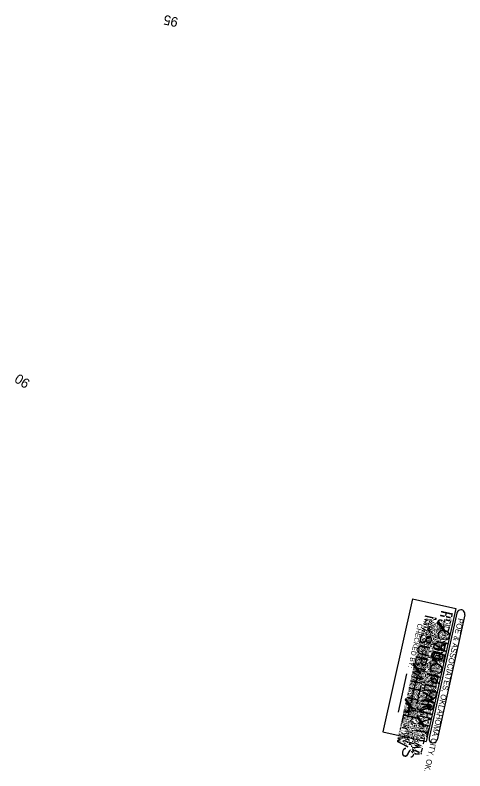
# Model space of a CAD drawing. Extents: x 2149887 to 2151449, y 143603 to 146901.
# Drawn here: x 2150415 to 2150971, y 143603 to 144538 of the extents above; entities that cross this region are included whole.
import ezdxf

# ---------------------------------------------------------------- set-up
doc = ezdxf.new("R2010")
doc.units = 0
for name, color, linetype in [('SHT_Stamp_30_Submit', 7, 'Continuous'), ('SHT_Stamp_70_Submit', 7, 'Continuous'), ('SHT_Stamp_Check_Print', 7, 'Continuous'), ('SHT_Stamp_Est_Inf', 7, 'Continuous'), ('SHT_Stamp_FFR', 7, 'Continuous'), ('SHT_Stamp_Info_Material', 7, 'Continuous'), ('SHT_Stamp_No_Const', 7, 'Continuous'), ('SHT_Stamp_No_Design', 7, 'Continuous'), ('SHT_Stamp_Plan_Hand', 7, 'Continuous'), ('SHT_Stamp_Pre_Plan', 7, 'Continuous'), ('SHT_Stamp_Prop_RW', 7, 'Continuous'), ('SHT_Stamp_Ret_Sub', 7, 'Continuous'), ('SHT_Stamp_Rev_Prop_RW', 7, 'Continuous'), ('SHT_Stamp_Rev_Sheet', 7, 'Continuous'), ('SHT_Stamp_RW_Utilities_Meeting', 7, 'Continuous'), ('SHT_Stamp_RW_Utilities_Review', 7, 'Continuous'), ('SHT_Stamp_Send_Comments', 7, 'Continuous'), ('TOPO_DRAIN_Manhole', 7, 'Continuous')]:
    doc.layers.add(name, color=color, linetype=linetype)

msp = doc.modelspace()

# ---------------------------------------------------------------- linework, layer by layer
at = {"layer": 'SHT_Stamp_30_Submit'}
for p, q in [((2150906.22, 143815.49), (2150869.69, 143651.21)), ((2150906.22, 143815.49), (2150959.86, 143803.56)), ((2150959.86, 143803.56), (2150923.34, 143639.28)), ((2150961.22, 143798.13), (2150926.86, 143643.62)), ((2150970.98, 143795.96), (2150936.62, 143641.44)), ((2150929.87, 143746.55), (2150929.53, 143745.06)), ((2150929.53, 143745.06), (2150936.27, 143735.59)), ((2150929.62, 143745.44), (2150936.35, 143735.98)), ((2150929.67, 143745.68), (2150936.41, 143736.22)), ((2150929.87, 143746.55), (2150936.6, 143737.09)), ((2150936.6, 143737.09), (2150936.27, 143735.59)), ((2150869.69, 143651.21), (2150923.34, 143639.28))]:
    msp.add_line(p, q, dxfattribs=at)
for centre, start, end in [((2150966.11, 143797.04), 347.45904, 167.46382), ((2150931.75, 143642.51), 167.46382, 347.4686)]:
    msp.add_arc(centre, 5, start, end, dxfattribs=at)
at = {"layer": 'SHT_Stamp_70_Submit'}
for p, q in [((2150906.22, 143815.49), (2150869.69, 143651.21)), ((2150906.22, 143815.49), (2150959.86, 143803.56)), ((2150959.86, 143803.56), (2150923.34, 143639.28)), ((2150961.22, 143798.13), (2150926.86, 143643.62)), ((2150970.98, 143795.96), (2150936.62, 143641.44)), ((2150929.87, 143746.55), (2150929.53, 143745.06)), ((2150929.53, 143745.06), (2150936.27, 143735.59)), ((2150929.62, 143745.44), (2150936.35, 143735.98)), ((2150929.67, 143745.68), (2150936.41, 143736.22)), ((2150929.87, 143746.55), (2150936.6, 143737.09)), ((2150936.6, 143737.09), (2150936.27, 143735.59)), ((2150869.69, 143651.21), (2150923.34, 143639.28))]:
    msp.add_line(p, q, dxfattribs=at)
for centre, start, end in [((2150966.11, 143797.04), 347.45904, 167.46382), ((2150931.75, 143642.51), 167.46382, 347.4686)]:
    msp.add_arc(centre, 5, start, end, dxfattribs=at)
at = {"layer": 'SHT_Stamp_Check_Print'}
for p, q in [((2150906.22, 143815.49), (2150869.69, 143651.21)), ((2150906.22, 143815.49), (2150959.86, 143803.56)), ((2150959.86, 143803.56), (2150923.34, 143639.28)), ((2150961.22, 143798.13), (2150926.86, 143643.62)), ((2150970.98, 143795.96), (2150936.62, 143641.44)), ((2150899.04, 143722.75), (2150888.5, 143675.39)), ((2150911.51, 143719.98), (2150900.98, 143672.62)), ((2150869.69, 143651.21), (2150923.34, 143639.28))]:
    msp.add_line(p, q, dxfattribs=at)
for centre, start, end in [((2150966.11, 143797.04), 347.45904, 167.46382), ((2150931.75, 143642.51), 167.46382, 347.4686)]:
    msp.add_arc(centre, 5, start, end, dxfattribs=at)
at = {"layer": 'SHT_Stamp_Est_Inf'}
for p, q in [((2150906.22, 143815.49), (2150869.69, 143651.21)), ((2150906.22, 143815.49), (2150959.86, 143803.56)), ((2150959.86, 143803.56), (2150923.34, 143639.28)), ((2150961.22, 143798.13), (2150926.86, 143643.62)), ((2150970.98, 143795.96), (2150936.62, 143641.44)), ((2150869.69, 143651.21), (2150923.34, 143639.28))]:
    msp.add_line(p, q, dxfattribs=at)
for centre, start, end in [((2150966.11, 143797.04), 347.45904, 167.46382), ((2150931.75, 143642.51), 167.46382, 347.4686)]:
    msp.add_arc(centre, 5, start, end, dxfattribs=at)
at = {"layer": 'SHT_Stamp_FFR'}
for p, q in [((2150906.22, 143815.49), (2150869.69, 143651.21)), ((2150906.22, 143815.49), (2150959.86, 143803.56)), ((2150959.86, 143803.56), (2150923.34, 143639.28)), ((2150961.22, 143798.13), (2150926.86, 143643.62)), ((2150970.98, 143795.96), (2150936.62, 143641.44)), ((2150869.69, 143651.21), (2150923.34, 143639.28))]:
    msp.add_line(p, q, dxfattribs=at)
for centre, start, end in [((2150966.11, 143797.04), 347.45904, 167.46382), ((2150931.75, 143642.51), 167.46382, 347.4686)]:
    msp.add_arc(centre, 5, start, end, dxfattribs=at)
at = {"layer": 'SHT_Stamp_Info_Material'}
for p, q in [((2150906.22, 143815.49), (2150869.69, 143651.21)), ((2150906.22, 143815.49), (2150959.86, 143803.56)), ((2150959.86, 143803.56), (2150923.34, 143639.28)), ((2150961.22, 143798.13), (2150926.86, 143643.62)), ((2150970.98, 143795.96), (2150936.62, 143641.44)), ((2150869.69, 143651.21), (2150923.34, 143639.28))]:
    msp.add_line(p, q, dxfattribs=at)
for centre, start, end in [((2150966.11, 143797.04), 347.45904, 167.46382), ((2150931.75, 143642.51), 167.46382, 347.4686)]:
    msp.add_arc(centre, 5, start, end, dxfattribs=at)
at = {"layer": 'SHT_Stamp_No_Const'}
for p, q in [((2150906.22, 143815.49), (2150869.69, 143651.21)), ((2150906.22, 143815.49), (2150959.86, 143803.56)), ((2150959.86, 143803.56), (2150923.34, 143639.28)), ((2150961.22, 143798.13), (2150926.86, 143643.62)), ((2150970.98, 143795.96), (2150936.62, 143641.44)), ((2150869.69, 143651.21), (2150923.34, 143639.28))]:
    msp.add_line(p, q, dxfattribs=at)
for centre, start, end in [((2150966.11, 143797.04), 347.45904, 167.46382), ((2150931.75, 143642.51), 167.46382, 347.4686)]:
    msp.add_arc(centre, 5, start, end, dxfattribs=at)
at = {"layer": 'SHT_Stamp_No_Design'}
for p, q in [((2150906.22, 143815.49), (2150869.69, 143651.21)), ((2150906.22, 143815.49), (2150959.86, 143803.56)), ((2150959.86, 143803.56), (2150923.34, 143639.28)), ((2150961.22, 143798.13), (2150926.86, 143643.62)), ((2150970.98, 143795.96), (2150936.62, 143641.44)), ((2150869.69, 143651.21), (2150923.34, 143639.28))]:
    msp.add_line(p, q, dxfattribs=at)
for centre, start, end in [((2150966.11, 143797.04), 347.45904, 167.46382), ((2150931.75, 143642.51), 167.46382, 347.4686)]:
    msp.add_arc(centre, 5, start, end, dxfattribs=at)
at = {"layer": 'SHT_Stamp_Plan_Hand'}
for p, q in [((2150906.22, 143815.49), (2150869.69, 143651.21)), ((2150906.22, 143815.49), (2150959.86, 143803.56)), ((2150959.86, 143803.56), (2150923.34, 143639.28)), ((2150961.22, 143798.13), (2150926.86, 143643.62)), ((2150970.98, 143795.96), (2150936.62, 143641.44)), ((2150869.69, 143651.21), (2150923.34, 143639.28))]:
    msp.add_line(p, q, dxfattribs=at)
for centre, start, end in [((2150966.11, 143797.04), 347.45904, 167.46382), ((2150931.75, 143642.51), 167.46382, 347.4686)]:
    msp.add_arc(centre, 5, start, end, dxfattribs=at)
at = {"layer": 'SHT_Stamp_Pre_Plan'}
for p, q in [((2150906.22, 143815.49), (2150869.69, 143651.21)), ((2150906.22, 143815.49), (2150959.86, 143803.56)), ((2150959.86, 143803.56), (2150923.34, 143639.28)), ((2150961.22, 143798.13), (2150926.86, 143643.62)), ((2150970.98, 143795.96), (2150936.62, 143641.44)), ((2150869.69, 143651.21), (2150923.34, 143639.28))]:
    msp.add_line(p, q, dxfattribs=at)
for centre, start, end in [((2150966.11, 143797.04), 347.45904, 167.46382), ((2150931.75, 143642.51), 167.46382, 347.4686)]:
    msp.add_arc(centre, 5, start, end, dxfattribs=at)
at = {"layer": 'SHT_Stamp_Prop_RW'}
for p, q in [((2150906.22, 143815.49), (2150869.69, 143651.21)), ((2150906.22, 143815.49), (2150959.86, 143803.56)), ((2150959.86, 143803.56), (2150923.34, 143639.28)), ((2150961.22, 143798.13), (2150926.86, 143643.62)), ((2150970.98, 143795.96), (2150936.62, 143641.44)), ((2150907.58, 143735.96), (2150907.17, 143734.11)), ((2150907.17, 143734.11), (2150915.48, 143722.43)), ((2150907.27, 143734.58), (2150915.59, 143722.9)), ((2150907.34, 143734.88), (2150915.65, 143723.2)), ((2150907.58, 143735.96), (2150915.89, 143724.27)), ((2150915.89, 143724.27), (2150915.48, 143722.43)), ((2150869.69, 143651.21), (2150923.34, 143639.28))]:
    msp.add_line(p, q, dxfattribs=at)
for centre, start, end in [((2150966.11, 143797.04), 347.45904, 167.46382), ((2150931.75, 143642.51), 167.46382, 347.4686)]:
    msp.add_arc(centre, 5, start, end, dxfattribs=at)
at = {"layer": 'SHT_Stamp_Ret_Sub'}
for p, q in [((2150906.22, 143815.49), (2150869.69, 143651.21)), ((2150906.22, 143815.49), (2150959.86, 143803.56)), ((2150959.86, 143803.56), (2150923.34, 143639.28)), ((2150961.22, 143798.13), (2150926.86, 143643.62)), ((2150970.98, 143795.96), (2150936.62, 143641.44)), ((2150869.69, 143651.21), (2150923.34, 143639.28))]:
    msp.add_line(p, q, dxfattribs=at)
for centre, start, end in [((2150966.11, 143797.04), 347.45904, 167.46382), ((2150931.75, 143642.51), 167.46382, 347.4686)]:
    msp.add_arc(centre, 5, start, end, dxfattribs=at)
at = {"layer": 'SHT_Stamp_Rev_Prop_RW'}
for p, q in [((2150906.22, 143815.49), (2150869.69, 143651.21)), ((2150906.22, 143815.49), (2150959.86, 143803.56)), ((2150959.86, 143803.56), (2150923.34, 143639.28)), ((2150961.22, 143798.13), (2150926.86, 143643.62)), ((2150970.98, 143795.96), (2150936.62, 143641.44)), ((2150897.78, 143692.54), (2150897.37, 143690.7)), ((2150897.37, 143690.7), (2150905.68, 143679.01)), ((2150897.47, 143691.17), (2150905.79, 143679.48)), ((2150897.54, 143691.47), (2150905.85, 143679.78)), ((2150897.78, 143692.54), (2150906.09, 143680.86)), ((2150906.09, 143680.86), (2150905.68, 143679.01)), ((2150869.69, 143651.21), (2150923.34, 143639.28))]:
    msp.add_line(p, q, dxfattribs=at)
for centre, start, end in [((2150966.11, 143797.04), 347.45904, 167.46382), ((2150931.75, 143642.51), 167.46382, 347.4686)]:
    msp.add_arc(centre, 5, start, end, dxfattribs=at)
at = {"layer": 'SHT_Stamp_Rev_Sheet'}
for p, q in [((2150906.22, 143815.49), (2150869.69, 143651.21)), ((2150906.22, 143815.49), (2150959.86, 143803.56)), ((2150959.86, 143803.56), (2150923.34, 143639.28)), ((2150961.22, 143798.13), (2150926.86, 143643.62)), ((2150970.98, 143795.96), (2150936.62, 143641.44)), ((2150869.69, 143651.21), (2150923.34, 143639.28))]:
    msp.add_line(p, q, dxfattribs=at)
for centre, start, end in [((2150966.11, 143797.04), 347.45904, 167.46382), ((2150931.75, 143642.51), 167.46382, 347.4686)]:
    msp.add_arc(centre, 5, start, end, dxfattribs=at)
at = {"layer": 'SHT_Stamp_RW_Utilities_Meeting'}
for p, q in [((2150906.22, 143815.49), (2150869.69, 143651.21)), ((2150906.22, 143815.49), (2150959.86, 143803.56)), ((2150959.86, 143803.56), (2150923.34, 143639.28)), ((2150961.22, 143798.13), (2150926.86, 143643.62)), ((2150970.98, 143795.96), (2150936.62, 143641.44)), ((2150937.91, 143787.85), (2150937.5, 143786.01)), ((2150937.91, 143787.85), (2150946.22, 143776.17)), ((2150937.5, 143786.01), (2150945.81, 143774.32)), ((2150937.6, 143786.48), (2150945.92, 143774.79)), ((2150937.67, 143786.78), (2150945.98, 143775.1)), ((2150946.22, 143776.17), (2150945.81, 143774.32)), ((2150869.69, 143651.21), (2150923.34, 143639.28))]:
    msp.add_line(p, q, dxfattribs=at)
for centre, start, end in [((2150966.11, 143797.04), 347.45904, 167.46382), ((2150931.75, 143642.51), 167.46382, 347.4686)]:
    msp.add_arc(centre, 5, start, end, dxfattribs=at)
at = {"layer": 'SHT_Stamp_RW_Utilities_Review'}
for p, q in [((2150906.22, 143815.49), (2150869.69, 143651.21)), ((2150906.22, 143815.49), (2150959.86, 143803.56)), ((2150959.86, 143803.56), (2150923.34, 143639.28)), ((2150961.22, 143798.13), (2150926.86, 143643.62)), ((2150970.98, 143795.96), (2150936.62, 143641.44)), ((2150911.98, 143671.26), (2150911.57, 143669.42)), ((2150911.57, 143669.42), (2150919.89, 143657.73)), ((2150911.68, 143669.89), (2150919.99, 143658.2)), ((2150911.74, 143670.19), (2150920.06, 143658.5)), ((2150911.98, 143671.26), (2150920.3, 143659.58)), ((2150920.3, 143659.58), (2150919.89, 143657.73)), ((2150869.69, 143651.21), (2150923.34, 143639.28))]:
    msp.add_line(p, q, dxfattribs=at)
for centre, start, end in [((2150966.11, 143797.04), 347.45904, 167.46382), ((2150931.75, 143642.51), 167.46382, 347.4686)]:
    msp.add_arc(centre, 5, start, end, dxfattribs=at)
at = {"layer": 'SHT_Stamp_Send_Comments'}
for p, q in [((2150906.22, 143815.49), (2150869.69, 143651.21)), ((2150906.22, 143815.49), (2150959.86, 143803.56)), ((2150959.86, 143803.56), (2150923.34, 143639.28)), ((2150961.22, 143798.13), (2150926.86, 143643.62)), ((2150970.98, 143795.96), (2150936.62, 143641.44)), ((2150869.69, 143651.21), (2150923.34, 143639.28))]:
    msp.add_line(p, q, dxfattribs=at)
for centre, start, end in [((2150966.11, 143797.04), 347.45904, 167.46382), ((2150931.75, 143642.51), 167.46382, 347.4686)]:
    msp.add_arc(centre, 5, start, end, dxfattribs=at)

# ---------------------------------------------------------------- texts
at = {"layer": 'SHT_Stamp_30_Submit'}
for s, height, p in [('POE & ASSOCIATES, OKLAHOMA CITY, OK.', 7, (2150962.83, 143792.14)), ('SUBMITTAL', 15, (2150916.91, 143773.61)), ('30   PLAN', 15, (2150933.38, 143763.23)), ('O', 7.65, (2150934.38, 143747.31)), ('O', 7.65, (2150928.62, 143740.81))]:
    msp.add_text(s, height=height, rotation=257.46382, dxfattribs=at).set_placement(p)
at = {"layer": 'SHT_Stamp_70_Submit'}
for s, height, p in [('POE & ASSOCIATES, OKLAHOMA CITY, OK.', 7, (2150962.83, 143792.14)), ('SUBMITTAL', 15, (2150916.91, 143773.61)), ('70   PLAN', 15, (2150933.46, 143763.58)), ('O', 7.65, (2150934.38, 143747.31)), ('O', 7.65, (2150928.62, 143740.81))]:
    msp.add_text(s, height=height, rotation=257.46382, dxfattribs=at).set_placement(p)
at = {"layer": 'SHT_Stamp_Check_Print'}
for s, height, p in [('POE & ASSOCIATES, OKLAHOMA CITY, OK.', 7, (2150962.84, 143792.13)), ('CHECKED BY:', 6, (2150913.02, 143785.61)), ('REVISED BY:', 6, (2150925.47, 143782.84)), ('CHECK PRINT', 15, (2150939.3, 143779.83))]:
    msp.add_text(s, height=height, rotation=257.46382, dxfattribs=at).set_placement(p)
at = {"layer": 'SHT_Stamp_Est_Inf'}
for s, height, p in [('POE & ASSOCIATES, OKLAHOMA CITY, OK.', 7, (2150962.84, 143792.13)), ('INFORMATION', 15, (2150919.28, 143784.28)), ('BASED ON EST.', 15, (2150938.5, 143786.23))]:
    msp.add_text(s, height=height, rotation=257.46382, dxfattribs=at).set_placement(p)
at = {"layer": 'SHT_Stamp_FFR'}
for s, height, p in [('POE & ASSOCIATES, OKLAHOMA CITY, OK.', 7, (2150962.84, 143792.13)), ('FINAL FIELD', 15, (2150936.1, 143775.45)), ('REVIEW', 15, (2150913.56, 143758.57))]:
    msp.add_text(s, height=height, rotation=257.46382, dxfattribs=at).set_placement(p)
at = {"layer": 'SHT_Stamp_Info_Material'}
for s, height, p in [('MATERIAL ONLY', 15, (2150922.09, 143796.9)), ('POE & ASSOCIATES, OKLAHOMA CITY, OK.', 7, (2150962.84, 143792.13)), ('INFORMATION', 15, (2150937.18, 143780.3))]:
    msp.add_text(s, height=height, rotation=257.46382, dxfattribs=at).set_placement(p)
at = {"layer": 'SHT_Stamp_No_Const'}
for s, height, p in [('NOT TO BE USED', 15, (2150940.56, 143795.52)), ('POE & ASSOCIATES, OKLAHOMA CITY, OK.', 7, (2150962.84, 143792.13)), ('FOR CONST.', 15, (2150917.34, 143775.57))]:
    msp.add_text(s, height=height, rotation=257.46382, dxfattribs=at).set_placement(p)
at = {"layer": 'SHT_Stamp_No_Design'}
for s, height, p in [('NOT TO BE USED', 15, (2150940.56, 143795.52)), ('POE & ASSOCIATES, OKLAHOMA CITY, OK.', 7, (2150962.84, 143792.13)), ('FOR DESIGN', 15, (2150917.54, 143776.44))]:
    msp.add_text(s, height=height, rotation=257.46382, dxfattribs=at).set_placement(p)
at = {"layer": 'SHT_Stamp_Plan_Hand'}
for s, height, p in [('POE & ASSOCIATES, OKLAHOMA CITY, OK.', 7, (2150962.84, 143792.13)), ('PLAN-IN-HAND', 15, (2150928.97, 143785.63))]:
    msp.add_text(s, height=height, rotation=257.46382, dxfattribs=at).set_placement(p)
at = {"layer": 'SHT_Stamp_Pre_Plan'}
for s, height, p in [('POE & ASSOCIATES, OKLAHOMA CITY, OK.', 7, (2150962.84, 143792.13)), ('PRELIMINARY', 15, (2150937.01, 143779.55)), ('PLANS', 15, (2150912.52, 143753.9))]:
    msp.add_text(s, height=height, rotation=257.46382, dxfattribs=at).set_placement(p)
at = {"layer": 'SHT_Stamp_Prop_RW'}
for s, height, p in [('POE & ASSOCIATES, OKLAHOMA CITY, OK.', 7, (2150962.84, 143792.13)), ('PROPOSED', 15, (2150933.3, 143762.89)), ('R W', 15, (2150910.72, 143745.77))]:
    msp.add_text(s, height=height, rotation=257.46382, dxfattribs=at).set_placement(p)
at = {"layer": 'SHT_Stamp_Ret_Sub'}
for s, height, p in [('POE & ASSOCIATES, OKLAHOMA CITY, OK.', 7, (2150962.84, 143792.13)), ('RET. SUBMITTED', 15, (2150938.64, 143786.87)), ('MATERIALS', 15, (2150917.04, 143774.19))]:
    msp.add_text(s, height=height, rotation=257.46382, dxfattribs=at).set_placement(p)
at = {"layer": 'SHT_Stamp_Rev_Prop_RW'}
for s, height, p in [('POE & ASSOCIATES, OKLAHOMA CITY, OK.', 7, (2150962.84, 143792.13)), ('PROPOSED R W', 15, (2150920.38, 143789.23)), ('REVISED', 15, (2150931.92, 143756.66))]:
    msp.add_text(s, height=height, rotation=257.46382, dxfattribs=at).set_placement(p)
at = {"layer": 'SHT_Stamp_Rev_Sheet'}
for s, height, p in [('POE & ASSOCIATES, OKLAHOMA CITY, OK.', 7, (2150962.84, 143792.13)), ('REVISED SHEET', 15, (2150929.51, 143788.05))]:
    msp.add_text(s, height=height, rotation=257.46382, dxfattribs=at).set_placement(p)
at = {"layer": 'SHT_Stamp_RW_Utilities_Meeting'}
for s, height, p in [('R W & UTILITIES', 15, (2150941.06, 143797.76)), ('POE & ASSOCIATES, OKLAHOMA CITY, OK.', 7, (2150962.83, 143792.14)), ('MEETING', 15, (2150914.82, 143764.22))]:
    msp.add_text(s, height=height, rotation=257.46382, dxfattribs=at).set_placement(p)
at = {"layer": 'SHT_Stamp_RW_Utilities_Review'}
for s, height, p in [('PRELIMINARY R W', 15, (2150942.1, 143802.43)), ('& UTIL.  REVIEW', 15, (2150921.13, 143792.58)), ('POE & ASSOCIATES, OKLAHOMA CITY, OK.', 7, (2150962.83, 143792.14))]:
    msp.add_text(s, height=height, rotation=257.46382, dxfattribs=at).set_placement(p)
at = {"layer": 'SHT_Stamp_Send_Comments'}
for s, height, p in [('SEND COMMENTS', 15, (2150930.91, 143794.33)), ('POE & ASSOCIATES, OKLAHOMA CITY, OK.', 7, (2150962.84, 143792.13))]:
    msp.add_text(s, height=height, rotation=257.46382, dxfattribs=at).set_placement(p)
at = {"layer": 'TOPO_DRAIN_Manhole'}
for s, rotation, p in [('95', 167.58076, (2150617.26, 144534.44)), ('90', 147.58076, (2150434.23, 144085.33))]:
    msp.add_text(s, height=12, rotation=rotation, dxfattribs=at).set_placement(p)

doc.saveas('drawing.dxf')
